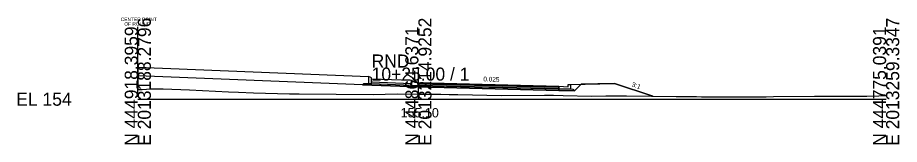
# Model space of a CAD drawing. Extents: x -26 to 163, y -10 to 7518.
# Drawn here: x -25.7 to 162.8, y 490.3 to 517.5 of the extents above; entities that cross this region are included whole.
import ezdxf

# ---------------------------------------------------------------- set-up
doc = ezdxf.new("R2010")
doc.units = 0
for name, color, linetype in [('Exist Cross Section Cell', 7, 'Continuous'), ('Exist XS Center Line Elevation Label', 7, 'Continuous'), ('Exist XS Ground Line', 7, 'Continuous'), ('Prop CMT Conc Surface', 7, 'Continuous'), ('Prop CMT Concrete Structures', 7, 'Continuous'), ('Prop CMT Pvmt Course 1', 7, 'Continuous'), ('Prop CMT Pvmt Course 1 CG', 7, 'Continuous'), ('Prop CMT Pvmt Course 2', 7, 'Continuous'), ('Prop CMT Pvmt Course 3', 7, 'Continuous'), ('Prop CMT Pvmt Surface', 7, 'Continuous'), ('Prop CMT Shear Line', 7, 'Continuous'), ('Prop CMT Shear Line Text', 7, 'Continuous'), ('Prop CMT Slope Grass', 7, 'Continuous'), ('Prop CMT Subgrade Earthwork', 7, 'Continuous'), ('Prop XS Earthwork Shape', 7, 'Continuous'), ('Prop XS SE Text', 7, 'Continuous'), ('Prop XS Side Slope Text', 7, 'Continuous')]:
    doc.layers.add(name, color=color, linetype=linetype)

msp = doc.modelspace()

# ---------------------------------------------------------------- linework, layer by layer
at = {"layer": 'Exist Cross Section Cell'}
for p, q in [((60, 500), (60, 506.79)), ((0, 500), (60, 500)), ((60, 500), (160, 500))]:
    msp.add_line(p, q, dxfattribs=at)
at = {"layer": 'Exist XS Ground Line'}
msp.add_lwpolyline([(0, 502.05), (0.91, 502.1), (2.78, 502.21), (3.68, 502.26), (4.21, 502.26), (5.04, 502.26), (5.42, 502.24), (11.07, 501.98), (19.37, 501.61), (21.55, 501.52), (24.71, 501.38), (32.43, 501.18), (34.5, 501.14), (50.33, 501.04), (55.43, 501.15), (60, 501.1), (64.81, 501.06), (66.59, 501.02), (68.4, 501.03), (77.75, 500.82), (86.94, 500.86), (88.91, 500.84), (90.92, 500.83), (97.04, 500.68), (100.07, 500.72), (104.5, 500.69), (115.14, 500.59), (118, 500.56), (119.48, 500.55), (120.51, 500.54), (128.97, 500.53), (133.56, 500.53), (134.36, 500.53), (135.96, 500.55), (144.72, 500.65), (149.28, 500.66), (155.89, 500.66), (158.48, 500.73), (160, 500.77)], dxfattribs=at)
at = {"layer": 'Prop CMT Conc Surface'}
for points in [[(50, 504.51), (49.96, 504.62), (49.85, 504.66), (49.34, 504.85)], [(50, 504.35), (50, 504.51)], [(60, 503.55), (59.25, 503.57), (59.25, 503.74), (58.5, 503.99)], [(90, 502.8), (91.99, 502.67)], [(91.99, 502.67), (91.99, 503.17), (92.49, 503.17)]]:
    msp.add_lwpolyline(points, dxfattribs=at)
at = {"layer": 'Prop CMT Concrete Structures'}
for points in [[(50, 504.51), (49.96, 504.62), (49.85, 504.66), (49.34, 504.85)], [(49.34, 504.85), (49.34, 503.35)], [(50, 504.35), (50, 504.51)], [(50, 503.35), (50, 504.35)], [(50, 504.35), (50, 503.76)], [(58.5, 503.99), (50, 504.33)], [(50, 503.74), (58.5, 503.4)], [(60, 503.55), (59.25, 503.57), (59.25, 503.74), (58.5, 503.99)], [(58.5, 503.99), (58.5, 503)], [(58.5, 503.4), (58.5, 503.99)], [(60, 502.97), (60, 503.55)], [(49.34, 503.35), (50, 503.35)], [(58.5, 503), (60, 502.97)], [(90, 502.8), (91.99, 502.67), (91.99, 503.17), (92.49, 503.17)], [(92.49, 503.17), (92.49, 502.15), (90, 502.21)], [(90, 502.21), (90, 502.8)]]:
    msp.add_lwpolyline(points, dxfattribs=at)
at = {"layer": 'Prop CMT Pvmt Course 1'}
for points in [[(60, 503.55), (90, 502.8)], [(60, 503.3), (60, 503.55)], [(90, 502.55), (60, 503.3)], [(90, 502.8), (90, 502.55)]]:
    msp.add_lwpolyline(points, dxfattribs=at)
msp.add_lwpolyline([(60, 503.3), (60, 503.42), (60, 503.42), (60, 503.3)], close=True, dxfattribs=at)
at = {"layer": 'Prop CMT Pvmt Course 1 CG'}
for points in [[(60, 502.63), (60, 502.97)], [(90, 502.21), (92.99, 502.14), (93.33, 501.8)], [(90, 501.88), (90, 502.21)], [(93.41, 501.79), (90, 501.88)]]:
    msp.add_lwpolyline(points, dxfattribs=at)
at = {"layer": 'Prop CMT Pvmt Course 2'}
for points in [[(60, 502.97), (60, 503.3)], [(60, 503.3), (90, 502.55)], [(90, 502.21), (60, 502.97)], [(90, 502.55), (90, 502.21)]]:
    msp.add_lwpolyline(points, dxfattribs=at)
at = {"layer": 'Prop CMT Pvmt Course 3'}
for points in [[(50, 503.35), (58.5, 503)], [(60, 502.97), (90, 502.21)], [(60, 502.63), (60, 502.97)], [(90, 501.88), (60, 502.63)], [(90, 502.21), (90, 501.88)]]:
    msp.add_lwpolyline(points, dxfattribs=at)
at = {"layer": 'Prop CMT Pvmt Surface'}
msp.add_lwpolyline([(60, 503.55), (90, 502.8)], dxfattribs=at)
at = {"layer": 'Prop CMT Shear Line'}
msp.add_line((0, 500.49), (0, 515.49), dxfattribs=at)
at = {"layer": 'Prop CMT Slope Grass'}
for p, q in [((49.34, 504.83), (0, 506.8)), ((48.06, 503.11), (0, 505.03))]:
    msp.add_line(p, q, dxfattribs=at)
msp.add_lwpolyline([(92.49, 503.17), (101.96, 503.36), (110.11, 500.64)], dxfattribs=at)
at = {"layer": 'Prop CMT Subgrade Earthwork'}
for p, q in [((0, 506.8), (0, 502.05)), ((48.34, 503.39), (48.06, 503.11))]:
    msp.add_line(p, q, dxfattribs=at)
for points in [[(48.34, 503.39), (49.34, 503.35)], [(48.06, 503.11), (60, 502.63)], [(60, 502.63), (90, 501.88)], [(90, 501.88), (93.41, 501.79), (94.83, 503.21)]]:
    msp.add_lwpolyline(points, dxfattribs=at)
at = {"layer": 'Prop XS Earthwork Shape'}
msp.add_lwpolyline([(104.5, 500.69), (110.11, 500.64), (101.96, 503.36), (94.83, 503.21), (93.41, 501.79), (90, 501.88), (60, 502.63), (48.06, 503.11), (0, 505.03), (0, 502.05), (0.91, 502.1), (2.78, 502.21), (3.68, 502.26), (4.21, 502.26), (5.04, 502.26), (5.42, 502.24), (11.07, 501.98), (19.37, 501.61), (21.55, 501.52), (24.71, 501.38), (32.43, 501.18), (34.5, 501.14), (50.33, 501.04), (55.43, 501.15), (60, 501.1), (64.81, 501.06), (66.59, 501.02), (68.4, 501.03), (77.75, 500.82), (86.94, 500.86), (88.91, 500.84), (90.92, 500.83), (97.04, 500.68), (100.07, 500.72)], close=True, dxfattribs=at)

# ---------------------------------------------------------------- texts
at = {"layer": 'Exist Cross Section Cell'}
for s, p in [('E 2013188.2796', (2.8, 490)), ('E 2013214.9252', (62.8, 490)), ('E 2013259.3347', (162.8, 490)), ('N 444918.3959', (0, 490)), ('N 444864.6371', (60, 490)), ('N 444775.0391', (160, 490))]:
    msp.add_text(s, height=2.8, rotation=90, dxfattribs=at).set_placement(p)
for s, p in [('RND', (50, 506.79)), ('10+25.00 / 1', (50, 503.99)), ('EL 154', (-26, 498.6))]:
    msp.add_text(s, height=2.8, dxfattribs=at).set_placement(p)
at = {"layer": 'Exist XS Center Line Elevation Label'}
msp.add_text('155.10', height=2, dxfattribs=at).set_placement((56.19, 496.1))
at = {"layer": 'Prop CMT Shear Line Text'}
for s, p in [('CENTER POINT', (-3.64, 516.75)), ('OF ROUND', (-2.88, 515.77))]:
    msp.add_text(s, height=0.75, dxfattribs=at).set_placement(p)
at = {"layer": 'Prop XS SE Text'}
msp.add_text('0.025', height=1, rotation=358.5613, dxfattribs=at).set_placement((73.87, 503.83))
at = {"layer": 'Prop XS Side Slope Text'}
msp.add_text('3:1', height=1, rotation=341.5651, dxfattribs=at).set_placement((105.53, 502.74))

doc.saveas('drawing.dxf')
